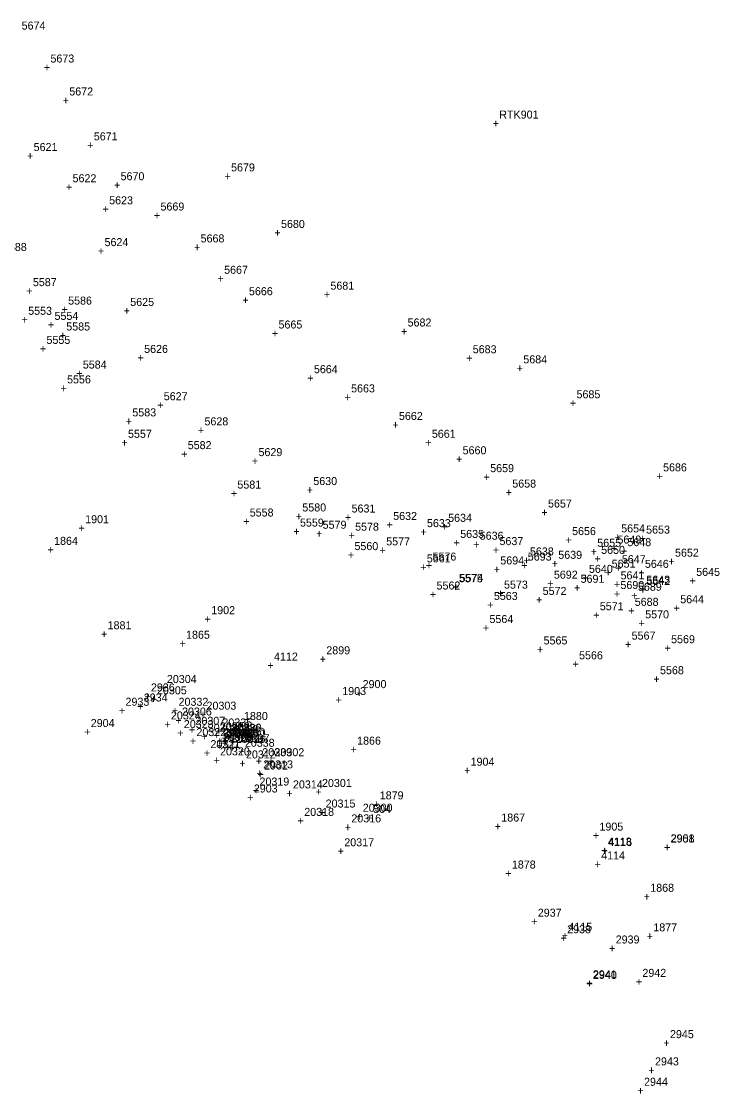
# Model space of a CAD drawing. Extents: x 1036751 to 1042192, y 772604 to 785439.
# Drawn here: x 1040463.6 to 1040681.7, y 775011.4 to 775346.1 of the extents above; entities that cross this region are included whole.
import ezdxf

# ---------------------------------------------------------------- set-up
doc = ezdxf.new("R2010")
doc.units = 0
for name, color, linetype in [('S_Buildings', 7, 'Continuous'), ('S_Buildings_SillElevation', 7, 'Continuous'), ('S_Control_Temp_Traverse', 7, 'Continuous'), ('S_Control_Traverse_Point', 7, 'Continuous'), ('S_Drainage_Waterway', 7, 'Continuous'), ('S_Ground_Elevation', 7, 'Continuous'), ('S_Property_IronPipeFound', 7, 'Continuous'), ('S_Roadway_Centerline', 7, 'Continuous'), ('S_Roadway_Edge_Pavement', 7, 'Continuous'), ('S_Roadway_Ledge_Outcrop', 7, 'Continuous'), ('S_Traffic_Sign_DoublePost', 7, 'Continuous'), ('S_Traffic_Sign_SinglePost', 7, 'Continuous'), ('S_Trees_Decid_Pay', 7, 'Continuous'), ('S_Utilities_GuyWire3', 7, 'Continuous'), ('S_Utilities_Hydrant', 7, 'Continuous'), ('S_Utilities_Pole_Power', 7, 'Continuous'), ('S_Utilities_Pole_Support3', 7, 'Continuous'), ('S_Utilities_UG_Water_Gate', 7, 'Continuous'), ('S_Utilities_UG_Water_Line', 7, 'Continuous')]:
    doc.layers.add(name, color=color, linetype=linetype)

msp = doc.modelspace()

# ---------------------------------------------------------------- texts
at = {"layer": 'S_Buildings'}
for s, p in [('2945', (1040666.18, 775028.68)), ('+', (1040664.12, 775025.93)), ('2944', (1040658.08, 775013.81)), ('+', (1040656.01, 775011.06))]:
    msp.add_text(s, height=2.5, dxfattribs=at).set_placement(p)
at = {"layer": 'S_Buildings_SillElevation'}
for s, p in [('2943', (1040661.51, 775020.17)), ('+', (1040659.44, 775017.42))]:
    msp.add_text(s, height=2.5, dxfattribs=at).set_placement(p)
at = {"layer": 'S_Control_Temp_Traverse'}
for s, p in [('RTK901', (1040612.86, 775315.78)), ('RTK901', (1040612.86, 775315.78)), ('+', (1040610.8, 775313.03)), ('+', (1040610.8, 775313.03))]:
    msp.add_text(s, height=2.5, dxfattribs=at).set_placement(p)
at = {"layer": 'S_Control_Traverse_Point'}
for s, p in [('504', (1040573.46, 775098.98)), ('504', (1040573.46, 775098.98)), ('504', (1040573.46, 775098.98)), ('504', (1040573.46, 775098.98)), ('504', (1040573.46, 775098.98)), ('504', (1040573.46, 775098.98)), ('504', (1040573.46, 775098.98)), ('+', (1040571.4, 775096.23)), ('+', (1040571.4, 775096.23)), ('+', (1040571.4, 775096.23)), ('+', (1040571.4, 775096.23)), ('+', (1040571.4, 775096.23)), ('+', (1040571.4, 775096.23)), ('+', (1040571.4, 775096.23))]:
    msp.add_text(s, height=2.5, dxfattribs=at).set_placement(p)
at = {"layer": 'S_Drainage_Waterway'}
for s, p in [('5553', (1040465.7, 775254.52)), ('5554', (1040473.93, 775252.93)), ('+', (1040463.64, 775251.77)), ('+', (1040471.87, 775250.18)), ('5555', (1040471.42, 775245.43)), ('+', (1040469.36, 775242.68)), ('5556', (1040477.85, 775233.1)), ('+', (1040475.79, 775230.35)), ('5557', (1040496.89, 775216.12)), ('+', (1040494.83, 775213.37)), ('+', (1040532.85, 775188.79)), ('5558', (1040534.91, 775191.54)), ('5559', (1040550.61, 775188.39)), ('+', (1040548.55, 775185.64)), ('5560', (1040567.62, 775181.05)), ('+', (1040565.56, 775178.3)), ('5561', (1040590.22, 775177.22)), ('+', (1040588.16, 775174.47)), ('5562', (1040593.26, 775168.74)), ('+', (1040591.2, 775165.99)), ('5563', (1040611.17, 775165.48)), ('+', (1040609.11, 775162.73)), ('5564', (1040609.79, 775158.28)), ('+', (1040607.73, 775155.53)), ('5565', (1040626.7, 775151.6)), ('5567', (1040654.21, 775153.11)), ('+', (1040624.64, 775148.85)), ('+', (1040652.14, 775150.36)), ('5566', (1040637.78, 775146.96)), ('+', (1040635.72, 775144.21)), ('5568', (1040663.07, 775142.3)), ('+', (1040661.01, 775139.55))]:
    msp.add_text(s, height=2.5, dxfattribs=at).set_placement(p)
at = {"layer": 'S_Ground_Elevation'}
for s, p in [('5674', (1040463.66, 775343.57)), ('5673', (1040472.66, 775333.28)), ('+', (1040470.6, 775330.53)), ('5672', (1040478.55, 775323)), ('+', (1040476.49, 775320.25)), ('5671', (1040486.2, 775308.99)), ('5621', (1040467.41, 775305.65)), ('+', (1040484.14, 775306.24)), ('+', (1040465.35, 775302.9)), ('5679', (1040529.08, 775299.29)), ('5622', (1040479.57, 775295.9)), ('5670', (1040494.57, 775296.53)), ('+', (1040527.02, 775296.54)), ('+', (1040477.51, 775293.15)), ('+', (1040492.51, 775293.78)), ('5623', (1040490.99, 775289.02)), ('+', (1040488.93, 775286.27)), ('5669', (1040507.03, 775287.07)), ('+', (1040504.97, 775284.32)), ('5680', (1040544.68, 775281.63)), ('5624', (1040489.56, 775275.96)), ('5668', (1040519.56, 775277.12)), ('+', (1040542.62, 775278.88)), ('5588', (1040457.82, 775274.45)), ('+', (1040487.5, 775273.21)), ('+', (1040517.5, 775274.37)), ('5667', (1040526.91, 775267.32)), ('5587', (1040467.16, 775263.47)), ('+', (1040524.84, 775264.57)), ('5681', (1040560.11, 775262.36)), ('+', (1040465.1, 775260.72)), ('5666', (1040534.67, 775260.63)), ('+', (1040558.04, 775259.61)), ('5586', (1040478.18, 775257.7)), ('5625', (1040497.59, 775257.28)), ('+', (1040532.61, 775257.88)), ('+', (1040476.12, 775254.95)), ('+', (1040495.53, 775254.53)), ('5585', (1040477.6, 775249.62)), ('5665', (1040543.9, 775250.24)), ('5682', (1040584.22, 775250.87)), ('+', (1040475.54, 775246.87)), ('+', (1040541.84, 775247.49)), ('+', (1040582.16, 775248.12)), ('5626', (1040501.93, 775242.61)), ('5683', (1040604.57, 775242.51)), ('+', (1040499.87, 775239.86)), ('+', (1040602.51, 775239.76)), ('5684', (1040620.37, 775239.36)), ('5584', (1040482.77, 775237.73)), ('5664', (1040554.95, 775236.29)), ('+', (1040618.31, 775236.61)), ('+', (1040480.71, 775234.98)), ('+', (1040552.89, 775233.54)), ('5663', (1040566.57, 775230.29)), ('5627', (1040508.05, 775227.84)), ('+', (1040564.5, 775227.54)), ('+', (1040634.93, 775225.7)), ('5685', (1040636.99, 775228.45)), ('5583', (1040498.24, 775222.8)), ('+', (1040505.99, 775225.09)), ('+', (1040496.18, 775220.05)), ('5628', (1040520.77, 775220)), ('+', (1040579.46, 775218.93)), ('5662', (1040581.52, 775221.68)), ('+', (1040518.71, 775217.25)), ('5661', (1040591.79, 775216.12)), ('5582', (1040515.54, 775212.57)), ('+', (1040589.73, 775213.37)), ('+', (1040513.48, 775209.82)), ('5629', (1040537.65, 775210.4)), ('5660', (1040601.41, 775210.97)), ('+', (1040535.58, 775207.65)), ('+', (1040599.35, 775208.22)), ('5659', (1040610.02, 775205.39)), ('5686', (1040664.02, 775205.64)), ('+', (1040607.96, 775202.64)), ('+', (1040661.96, 775202.89)), ('5581', (1040531.05, 775200.26)), ('5630', (1040554.77, 775201.36)), ('5658', (1040616.92, 775200.57)), ('+', (1040528.99, 775197.51)), ('+', (1040552.71, 775198.61)), ('+', (1040614.86, 775197.82)), ('5580', (1040551.34, 775193.12)), ('5631', (1040566.72, 775192.79)), ('5657', (1040628.08, 775194.34)), ('+', (1040549.28, 775190.37)), ('+', (1040564.66, 775190.04)), ('5632', (1040579.72, 775190.46)), ('5634', (1040596.89, 775189.88)), ('+', (1040626.02, 775191.59)), ('5579', (1040557.68, 775187.72)), ('5578', (1040567.82, 775187.11)), ('+', (1040577.66, 775187.71)), ('+', (1040588.21, 775185.48)), ('5633', (1040590.27, 775188.23)), ('+', (1040594.83, 775187.13)), ('5656', (1040635.6, 775185.74)), ('5654', (1040650.94, 775186.58)), ('5653', (1040658.73, 775186.2)), ('+', (1040555.61, 775184.97)), ('+', (1040565.76, 775184.36)), ('5577', (1040577.54, 775182.53)), ('+', (1040598.6, 775182.1)), ('5635', (1040600.66, 775184.85)), ('5636', (1040606.75, 775184.29)), ('5637', (1040612.92, 775182.61)), ('+', (1040633.54, 775182.99)), ('5655', (1040643.47, 775182.09)), ('+', (1040648.88, 775183.83)), ('5649', (1040649.77, 775183.1)), ('5648', (1040652.88, 775182.28)), ('+', (1040656.67, 775183.45)), ('+', (1040575.48, 775179.78)), ('+', (1040604.69, 775181.54)), ('+', (1040610.86, 775179.86)), ('5638', (1040622.44, 775179.38)), ('5639', (1040631.29, 775178.34)), ('+', (1040641.41, 775179.34)), ('5650', (1040644.68, 775179.87)), ('+', (1040647.71, 775180.35)), ('+', (1040650.82, 775179.53)), ('5652', (1040667.75, 775179)), ('5576', (1040592, 775177.78)), ('5694', (1040613.18, 775176.58)), ('+', (1040620.38, 775176.63)), ('5693', (1040621.76, 775177.78)), ('+', (1040629.23, 775175.59)), ('+', (1040642.62, 775177.12)), ('5651', (1040647.97, 775175.57)), ('5647', (1040651.14, 775176.97)), ('5646', (1040658.35, 775175.51)), ('+', (1040665.69, 775176.25)), ('+', (1040589.94, 775175.03)), ('+', (1040611.12, 775173.83)), ('+', (1040619.7, 775175.03)), ('5692', (1040629.91, 775172.14)), ('5640', (1040640.87, 775173.94)), ('+', (1040645.91, 775172.82)), ('+', (1040649.08, 775174.22)), ('5641', (1040650.74, 775171.92)), ('+', (1040656.29, 775172.76)), ('5645', (1040674.37, 775173)), ('5575', (1040600.26, 775171)), ('5574', (1040600.44, 775171.13)), ('5573', (1040614.34, 775169.03)), ('+', (1040627.85, 775169.39)), ('5691', (1040638.26, 775170.84)), ('+', (1040638.81, 775171.19)), ('+', (1040648.68, 775169.17)), ('5690', (1040650.7, 775168.91)), ('5689', (1040656.17, 775168.36)), ('5643', (1040658.79, 775170.57)), ('5642', (1040658.8, 775170.19)), ('+', (1040672.31, 775170.25)), ('+', (1040598.2, 775168.25)), ('+', (1040598.37, 775168.38)), ('+', (1040612.28, 775166.28)), ('5572', (1040626.41, 775167.06)), ('+', (1040636.2, 775168.09)), ('+', (1040648.64, 775166.16)), ('+', (1040654.1, 775165.61)), ('+', (1040656.73, 775167.82)), ('+', (1040656.74, 775167.44)), ('+', (1040624.35, 775164.31)), ('5571', (1040644.26, 775162.29)), ('5688', (1040655.17, 775163.65)), ('5644', (1040669.38, 775164.46)), ('+', (1040642.2, 775159.54)), ('+', (1040653.11, 775160.9)), ('5570', (1040658.44, 775159.74)), ('+', (1040667.31, 775161.71)), ('+', (1040656.38, 775156.99)), ('5569', (1040666.53, 775151.98)), ('+', (1040664.47, 775149.23)), ('20304', (1040509.03, 775139.56)), ('20305', (1040505.93, 775136.03)), ('+', (1040506.97, 775136.81)), ('+', (1040503.87, 775133.28)), ('20332', (1040512.67, 775132.45)), ('20324', (1040510.29, 775128.19)), ('+', (1040510.61, 775129.7)), ('20306', (1040513.76, 775129.4)), ('+', (1040519.35, 775128.49)), ('20303', (1040521.41, 775131.24)), ('+', (1040508.23, 775125.44)), ('+', (1040511.7, 775126.65)), ('20323', (1040514.32, 775125.48)), ('20307', (1040517.95, 775126.5)), ('20333', (1040525.57, 775124.78)), ('20335', (1040526.37, 775125.99)), ('+', (1040512.26, 775122.73)), ('+', (1040515.89, 775123.75)), ('20322', (1040518.26, 775122.98)), ('20308', (1040521.8, 775124.36)), ('+', (1040523.51, 775122.03)), ('+', (1040524.31, 775123.24)), ('20309', (1040526.49, 775121.49)), ('20334', (1040526.62, 775122.92)), ('20310', (1040528.23, 775122.32)), ('20336', (1040529.19, 775124.38)), ('+', (1040516.2, 775120.23)), ('+', (1040519.74, 775121.61)), ('20321', (1040522.64, 775119.23)), ('+', (1040524.43, 775118.74)), ('+', (1040524.56, 775120.17)), ('+', (1040526.17, 775119.57)), ('+', (1040527.13, 775121.63)), ('20311', (1040529.23, 775121.09)), ('20337', (1040531.8, 775121.07)), ('20338', (1040533.39, 775119.65)), ('+', (1040520.58, 775116.48)), ('20320', (1040525.64, 775116.96)), ('+', (1040527.17, 775118.34)), ('+', (1040529.74, 775118.32)), ('+', (1040531.33, 775116.9)), ('20312', (1040533.74, 775116.01)), ('20339', (1040538.84, 775116.71)), ('20302', (1040542.65, 775116.7)), ('+', (1040523.58, 775114.21)), ('+', (1040531.68, 775113.26)), ('+', (1040536.78, 775113.96)), ('20313', (1040539.12, 775112.9)), ('+', (1040540.59, 775113.95)), ('+', (1040537.05, 775110.15)), ('20319', (1040537.96, 775107.54)), ('20314', (1040548.41, 775106.65)), ('20301', (1040557.49, 775107.09)), ('+', (1040535.9, 775104.79)), ('+', (1040546.35, 775103.9)), ('+', (1040555.43, 775104.34)), ('20318', (1040551.94, 775098.07)), ('20315', (1040558.62, 775100.68)), ('20300', (1040570.22, 775099.37)), ('+', (1040549.87, 775095.32)), ('+', (1040556.55, 775097.93)), ('20316', (1040566.65, 775096.04)), ('+', (1040568.16, 775096.62)), ('+', (1040564.59, 775093.29)), ('20317', (1040564.45, 775088.58)), ('+', (1040562.38, 775085.83))]:
    msp.add_text(s, height=2.5, dxfattribs=at).set_placement(p)
at = {"layer": 'S_Property_IronPipeFound'}
for s, p in [('2933', (1040496.1, 775132.46)), ('+', (1040494.04, 775129.71)), ('2904', (1040485.25, 775125.81)), ('+', (1040483.19, 775123.06)), ('2941', (1040642.1, 775047.37)), ('+', (1040640.03, 775044.62))]:
    msp.add_text(s, height=2.5, dxfattribs=at).set_placement(p)
at = {"layer": 'S_Roadway_Centerline'}
for s, p in [('1864', (1040473.8, 775182.69)), ('+', (1040471.74, 775179.94)), ('1865', (1040515.02, 775153.38)), ('+', (1040512.96, 775150.63)), ('1866', (1040568.45, 775120.31)), ('+', (1040566.39, 775117.56)), ('1867', (1040613.48, 775096.3)), ('+', (1040611.42, 775093.55)), ('+', (1040657.96, 775071.63)), ('1868', (1040660.02, 775074.38))]:
    msp.add_text(s, height=2.5, dxfattribs=at).set_placement(p)
at = {"layer": 'S_Roadway_Edge_Pavement'}
for s, p in [('1901', (1040483.5, 775189.45)), ('+', (1040481.44, 775186.7)), ('1902', (1040522.88, 775161.05)), ('1881', (1040490.52, 775156.33)), ('+', (1040520.82, 775158.3)), ('+', (1040488.46, 775153.58)), ('1903', (1040563.8, 775135.8)), ('+', (1040561.73, 775133.05)), ('+', (1040531.05, 775125.26)), ('1880', (1040533.11, 775128.01)), ('1904', (1040603.91, 775113.74)), ('+', (1040601.85, 775110.99)), ('1879', (1040575.52, 775103.23)), ('+', (1040573.46, 775100.48)), ('1905', (1040644.15, 775093.48)), ('+', (1040642.09, 775090.73)), ('1878', (1040616.79, 775081.64)), ('+', (1040614.73, 775078.89)), ('1877', (1040660.98, 775062.02)), ('+', (1040658.92, 775059.27))]:
    msp.add_text(s, height=2.5, dxfattribs=at).set_placement(p)
at = {"layer": 'S_Roadway_Ledge_Outcrop'}
for s, p in [('20327', (1040526.99, 775122.93)), ('20328', (1040528.29, 775123.86)), ('20326', (1040528.47, 775122.8)), ('20329', (1040529.37, 775124.24)), ('20330', (1040530.5, 775122.89)), ('20331', (1040530.75, 775122.59)), ('+', (1040524.93, 775120.18)), ('+', (1040526.23, 775121.11)), ('+', (1040526.41, 775120.05)), ('+', (1040527.31, 775121.49)), ('+', (1040528.44, 775120.14)), ('+', (1040528.69, 775119.84)), ('20325', (1040530.51, 775120.87)), ('+', (1040528.45, 775118.12))]:
    msp.add_text(s, height=2.5, dxfattribs=at).set_placement(p)
at = {"layer": 'S_Traffic_Sign_DoublePost'}
for s, p in [('2936', (1040504.05, 775136.93)), ('2934', (1040501.81, 775133.79)), ('+', (1040501.98, 775134.18)), ('+', (1040499.75, 775131.04))]:
    msp.add_text(s, height=2.5, dxfattribs=at).set_placement(p)
at = {"layer": 'S_Traffic_Sign_SinglePost'}
for s, p in [('+', (1040568.11, 775135.21)), ('2900', (1040570.17, 775137.96)), ('2937', (1040624.89, 775066.6)), ('+', (1040622.83, 775063.85))]:
    msp.add_text(s, height=2.5, dxfattribs=at).set_placement(p)
at = {"layer": 'S_Trees_Decid_Pay'}
for s, p in [('2942', (1040657.57, 775047.81)), ('+', (1040655.51, 775045.06))]:
    msp.add_text(s, height=2.5, dxfattribs=at).set_placement(p)
at = {"layer": 'S_Utilities_GuyWire3'}
for s, p in [('2903', (1040536.18, 775105.38)), ('+', (1040534.11, 775102.63)), ('2940', (1040642.15, 775047.16)), ('+', (1040640.09, 775044.41))]:
    msp.add_text(s, height=2.5, dxfattribs=at).set_placement(p)
at = {"layer": 'S_Utilities_Hydrant'}
for s, p in [('2938', (1040634.06, 775061.43)), ('+', (1040632, 775058.68))]:
    msp.add_text(s, height=2.5, dxfattribs=at).set_placement(p)
at = {"layer": 'S_Utilities_Pole_Power'}
for s, p in [('2899', (1040558.83, 775148.53)), ('+', (1040556.77, 775145.78)), ('2901', (1040666.36, 775089.81)), ('2958', (1040666.43, 775089.76)), ('+', (1040664.3, 775087.06)), ('+', (1040664.37, 775087.01))]:
    msp.add_text(s, height=2.5, dxfattribs=at).set_placement(p)
at = {"layer": 'S_Utilities_Pole_Support3'}
for s, p in [('2902', (1040539.4, 775112.55)), ('+', (1040537.34, 775109.8)), ('2939', (1040649.22, 775058.23)), ('+', (1040647.16, 775055.48))]:
    msp.add_text(s, height=2.5, dxfattribs=at).set_placement(p)
at = {"layer": 'S_Utilities_UG_Water_Gate'}
for s, p in [('+', (1040642.64, 775081.74)), ('4114', (1040644.7, 775084.49))]:
    msp.add_text(s, height=2.5, dxfattribs=at).set_placement(p)
at = {"layer": 'S_Utilities_UG_Water_Line'}
for s, p in [('4112', (1040542.5, 775146.56)), ('+', (1040540.44, 775143.81)), ('4113', (1040646.78, 775088.8)), ('4116', (1040646.91, 775088.64)), ('+', (1040644.72, 775086.05)), ('+', (1040644.85, 775085.89)), ('4115', (1040634.45, 775062.19)), ('+', (1040632.38, 775059.44))]:
    msp.add_text(s, height=2.5, dxfattribs=at).set_placement(p)

doc.saveas('drawing.dxf')
